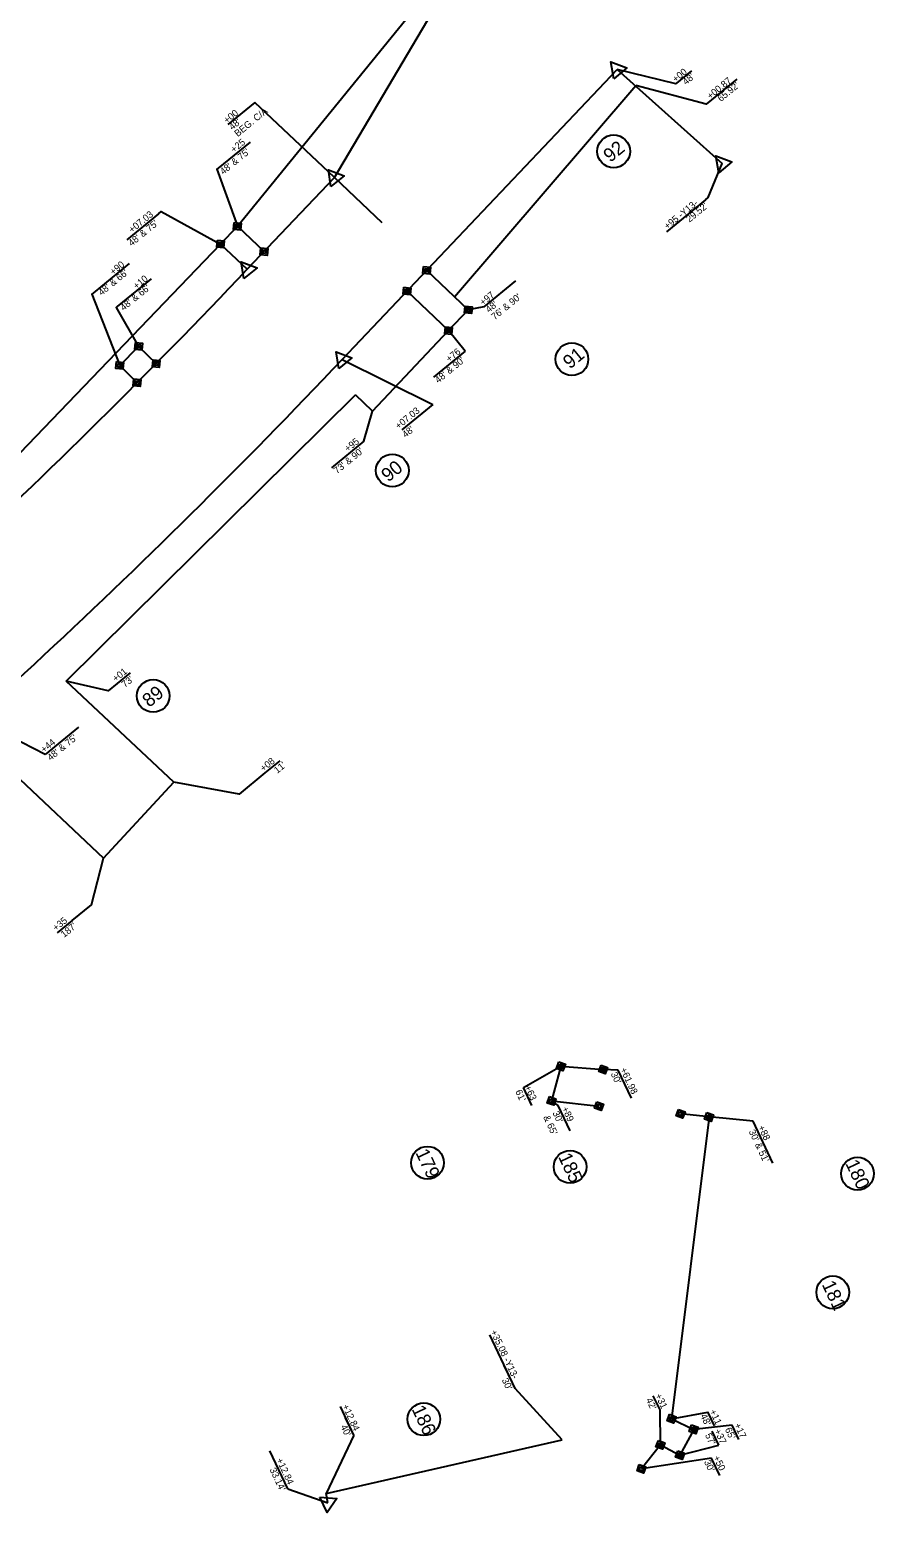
# Model space of a CAD drawing. Extents: x 2320946 to 2332748, y 597838 to 612698.
# Drawn here: x 2327112 to 2327731, y 601762 to 602867 of the extents above; entities that cross this region are included whole.
import ezdxf

# ---------------------------------------------------------------- set-up
doc = ezdxf.new("R2010")
doc.units = 0
for name, color, linetype in [('Prop Easement Construction', 7, 'Continuous'), ('Prop Easement Construction Station Offsets', 7, 'Continuous'), ('Prop Easement Permanent Drainage', 7, 'Continuous'), ('Prop Easement Permanent Drainage Station Offsets', 7, 'Continuous'), ('Prop Easement Permanent Utility', 7, 'Continuous'), ('Prop Easement Permanent Utility Station Offsets', 7, 'Continuous'), ('Prop Parcel Number CELL', 7, 'Continuous'), ('Prop ROW CA Lines', 7, 'Continuous'), ('Prop ROW Marker CELL', 7, 'Continuous'), ('Prop ROW Permanent Easement CELL', 7, 'Continuous'), ('Prop ROW RW CA Lines', 7, 'Continuous'), ('Prop ROW RW Lines', 7, 'Continuous'), ('Prop ROW Station Offsets', 7, 'Continuous')]:
    doc.layers.add(name, color=color, linetype=linetype)

msp = doc.modelspace()

# ---------------------------------------------------------------- linework, layer by layer
at = {"layer": 'Prop Easement Construction'}
for p, q in [((2327264.3, 602723.6), (2327447.9, 602949.2)), ((2327423.4, 602671.9), (2327556.4, 602826.8)), ((2327076.5, 602527.8), (2327252, 602710.5)), ((2327363.3, 602588.1), (2327419.1, 602647.1)), ((2327138.8, 602390.1), (2327350.9, 602599.9)), ((2327363.3, 602588.1), (2327350.9, 602599.9)), ((2327217.8, 602316), (2327138.8, 602390.1)), ((2327100.4, 602322.2), (2327166.1, 602260.3)), ((2327166.1, 602260.3), (2327217.8, 602316)), ((2327329.4, 601794.3), (2327502.5, 601833.7)), ((2327330.7, 601787.6), (2327329.4, 601794.3))]:
    msp.add_line(p, q, dxfattribs=at)
at = {"layer": 'Prop Easement Construction Station Offsets'}
for p, q in [((2327630.5, 602831.4), (2327611.9, 602816.2)), ((2327357.1, 602565.9), (2327333.4, 602546.4)), ((2327185.6, 602396.1), (2327176.1, 602388.3)), ((2327295.4, 602331.6), (2327284.5, 602322.7)), ((2327143.1, 602214.5), (2327132.3, 602205.6)), ((2327465.9, 601875.6), (2327459.9, 601888.3)), ((2327502.5, 601833.7), (2327467.9, 601871.3)), ((2327349.6, 601837.2), (2327343.7, 601849.9)), ((2327349.6, 601837.2), (2327329.4, 601794.3))]:
    msp.add_line(p, q, dxfattribs=at)
for points in [[(2327611.9, 602816.2), (2327608, 602813), (2327556.4, 602826.8)], [(2327357.1, 602565.9), (2327363.3, 602588.1)], [(2327176.1, 602388.3), (2327169.6, 602383), (2327138.8, 602390.1)], [(2327284.5, 602322.7), (2327265.6, 602307.2), (2327217.8, 602316)], [(2327143.1, 602214.5), (2327157.3, 602226.1), (2327166.1, 602260.3)], [(2327467.9, 601871.3), (2327449.3, 601910.7)], [(2327349.6, 601837.2), (2327339.8, 601858.1)]]:
    msp.add_lwpolyline(points, dxfattribs=at)
at = {"layer": 'Prop Easement Permanent Drainage'}
for p, q in [((2327252, 602710.5), (2327264.3, 602723.6)), ((2327264.3, 602723.6), (2327283.9, 602705)), ((2327252, 602710.5), (2327271.5, 602692)), ((2327178.1, 602621.5), (2327191.9, 602635.5)), ((2327191.9, 602635.5), (2327204.8, 602622.9)), ((2327178.1, 602621.5), (2327190.8, 602608.8))]:
    msp.add_line(p, q, dxfattribs=at)
at = {"layer": 'Prop Easement Permanent Drainage Station Offsets'}
for p, q in [((2327273.7, 602785.2), (2327250.3, 602766.2)), ((2327206.5, 602732.7), (2327183.2, 602713.7)), ((2327184.9, 602696.2), (2327160, 602675.8)), ((2327201, 602685), (2327176.1, 602664.7)), ((2327147.8, 602356.2), (2327123.4, 602336.3)), ((2327123.4, 602336.3), (2327097.7, 602349.4))]:
    msp.add_line(p, q, dxfattribs=at)
for points in [[(2327250.3, 602766.2), (2327249.3, 602765.4), (2327264.3, 602723.6)], [(2327206.5, 602732.7), (2327208.4, 602734.3), (2327252, 602710.5)], [(2327160, 602675.8), (2327157.6, 602673.9), (2327178.1, 602621.5)], [(2327176.1, 602664.7), (2327175.5, 602664.1), (2327191.9, 602635.5)]]:
    msp.add_lwpolyline(points, dxfattribs=at)
at = {"layer": 'Prop Easement Permanent Utility'}
for p, q in [((2327433.6, 602662.3), (2327403.1, 602691.2)), ((2327419.1, 602647.1), (2327388.7, 602676)), ((2327419.1, 602647.1), (2327433.6, 602662.3)), ((2327501.5, 602107.6), (2327494.7, 602082.2)), ((2327501.5, 602107.6), (2327532.4, 602105.2)), ((2327494.7, 602082.2), (2327529.5, 602078.4)), ((2327610.1, 602070.5), (2327582.6, 601849.2)), ((2327610.1, 602070.5), (2327589.2, 602072.8)), ((2327582.6, 601849.2), (2327598.9, 601841.4)), ((2327598.9, 601841.4), (2327588.8, 601822.5)), ((2327574.5, 601830), (2327560.5, 601812.4)), ((2327574.5, 601830), (2327588.8, 601822.5))]:
    msp.add_line(p, q, dxfattribs=at)
at = {"layer": 'Prop Easement Permanent Utility Station Offsets'}
for p, q in [((2327468.3, 602683.5), (2327445, 602664.4)), ((2327431.4, 602632.1), (2327408.1, 602613)), ((2327474, 602092.1), (2327501.5, 602107.6)), ((2327553.3, 602084.2), (2327543.6, 602104.8)), ((2327480.2, 602078.9), (2327474, 602092.1)), ((2327499.4, 602078.9), (2327494.7, 602082.2)), ((2327508.2, 602060.2), (2327499.4, 602078.9)), ((2327642.5, 602067.3), (2327610.1, 602070.5)), ((2327656.9, 602036.7), (2327642.5, 602067.3)), ((2327574.2, 601855.6), (2327569.2, 601866.1)), ((2327574.5, 601830), (2327574.2, 601855.6)), ((2327582.6, 601849.2), (2327609.2, 601854.1)), ((2327614, 601843.9), (2327609.1, 601854.3)), ((2327627.1, 601844.4), (2327598.9, 601841.4)), ((2327617.4, 601829.8), (2327612.5, 601840.2)), ((2327632, 601833.9), (2327627.1, 601844.4)), ((2327588.8, 601822.5), (2327617.4, 601829.8)), ((2327611.9, 601820.2), (2327560.5, 601812.4)), ((2327617.9, 601807.5), (2327611.9, 601820.2))]:
    msp.add_line(p, q, dxfattribs=at)
for points in [[(2327445, 602664.4), (2327433.6, 602662.3)], [(2327431.4, 602632.1), (2327419.1, 602647.1)], [(2327543.6, 602104.8), (2327532.4, 602105.2)]]:
    msp.add_lwpolyline(points, dxfattribs=at)
at = {"layer": 'Prop Parcel Number CELL'}
for p, q in [((2327540.2, 602778.5), (2327540.2, 602778.5)), ((2327509.6, 602626.1), (2327509.6, 602626.1)), ((2327377.9, 602544.5), (2327377.9, 602544.5)), ((2327202.6, 602379.2), (2327202.6, 602379.2)), ((2327403.7, 602036.9), (2327403.7, 602036.9)), ((2327508.2, 602033.9), (2327508.2, 602033.9)), ((2327718.9, 602028.9), (2327718.9, 602028.9)), ((2327700.8, 601941.9), (2327700.8, 601941.9)), ((2327401, 601848.8), (2327401, 601848.8))]:
    msp.add_line(p, q, dxfattribs=at)
for centre in [(2327540.2, 602778.5), (2327509.6, 602626.1), (2327377.9, 602544.5), (2327202.6, 602379.2), (2327403.7, 602036.9), (2327508.2, 602033.9), (2327718.9, 602028.9), (2327700.8, 601941.9), (2327401, 601848.8)]:
    msp.add_circle(centre, 12, dxfattribs=at)
at = {"layer": 'Prop ROW CA Lines'}
msp.add_line((2327335.5, 602759.4), (2327370.3, 602726.4), dxfattribs=at)
at = {"layer": 'Prop ROW Marker CELL'}
for p, q in [((2327542.8, 602838.5), (2327542.8, 602838.5)), ((2327619.8, 602769.5), (2327619.8, 602769.5)), ((2327335.5, 602759.4), (2327335.5, 602759.4)), ((2327264.3, 602723.6), (2327264.3, 602723.6)), ((2327252, 602710.5), (2327252, 602710.5)), ((2327283.9, 602705), (2327283.9, 602705)), ((2327271.5, 602692), (2327271.5, 602692)), ((2327403.1, 602691.2), (2327403.1, 602691.2)), ((2327388.7, 602676), (2327388.7, 602676)), ((2327433.6, 602662.3), (2327433.6, 602662.3)), ((2327419.1, 602647.1), (2327419.1, 602647.1)), ((2327191.9, 602635.5), (2327191.9, 602635.5)), ((2327178.1, 602621.5), (2327178.1, 602621.5)), ((2327204.8, 602622.9), (2327204.8, 602622.9)), ((2327341.2, 602625.9), (2327341.2, 602625.9)), ((2327190.8, 602608.8), (2327190.8, 602608.8)), ((2327501.5, 602107.6), (2327501.5, 602107.6)), ((2327532.4, 602105.2), (2327532.4, 602105.2)), ((2327494.7, 602082.2), (2327494.7, 602082.2)), ((2327529.5, 602078.4), (2327529.5, 602078.4)), ((2327589.2, 602072.8), (2327589.2, 602072.8)), ((2327610.1, 602070.5), (2327610.1, 602070.5)), ((2327582.6, 601849.2), (2327582.6, 601849.2)), ((2327598.9, 601841.4), (2327598.9, 601841.4)), ((2327574.5, 601830), (2327574.5, 601830)), ((2327560.5, 601812.4), (2327560.5, 601812.4)), ((2327588.8, 601822.5), (2327588.8, 601822.5)), ((2327330.7, 601787.6), (2327330.7, 601787.6))]:
    msp.add_line(p, q, dxfattribs=at)
for points in [[(2327540.2, 602831.8), (2327538.2, 602844.1), (2327549.9, 602839.7)], [(2327617.2, 602762.8), (2327615.2, 602775.1), (2327626.9, 602770.7)], [(2327332.9, 602752.7), (2327331, 602765), (2327342.6, 602760.6)], [(2327269, 602685.2), (2327267, 602697.5), (2327278.7, 602693.1)], [(2327338.6, 602619.2), (2327336.7, 602631.5), (2327348.3, 602627.1)], [(2327324.8, 601791.7), (2327337.2, 601790.7), (2327330.1, 601780.4)]]:
    msp.add_lwpolyline(points, close=True, dxfattribs=at)
at = {"layer": 'Prop ROW Permanent Easement CELL'}
for points in [[(2327262, 602726.4), (2327267.1, 602725.9), (2327266.6, 602720.8), (2327261.5, 602721.3)], [(2327263.2, 602725), (2327265.7, 602724.7), (2327265.5, 602722.2), (2327262.9, 602722.4)], [(2327249.7, 602713.3), (2327254.7, 602712.8), (2327254.2, 602707.8), (2327249.2, 602708.3)], [(2327250.8, 602711.9), (2327253.3, 602711.7), (2327253.1, 602709.1), (2327250.6, 602709.4)], [(2327281.6, 602707.8), (2327286.7, 602707.3), (2327286.2, 602702.2), (2327281.1, 602702.7)], [(2327282.8, 602706.4), (2327285.3, 602706.1), (2327285, 602703.6), (2327282.5, 602703.9)], [(2327400.8, 602694), (2327405.9, 602693.5), (2327405.4, 602688.4), (2327400.3, 602688.9)], [(2327402, 602692.6), (2327404.5, 602692.3), (2327404.3, 602689.8), (2327401.7, 602690.1)], [(2327386.4, 602678.8), (2327391.5, 602678.2), (2327390.9, 602673.2), (2327385.9, 602673.7)], [(2327387.5, 602677.4), (2327390.1, 602677.1), (2327389.8, 602674.6), (2327387.3, 602674.8)], [(2327431.3, 602665.1), (2327436.4, 602664.6), (2327435.9, 602659.5), (2327430.8, 602660)], [(2327432.5, 602663.7), (2327435, 602663.5), (2327434.7, 602660.9), (2327432.2, 602661.2)], [(2327416.9, 602649.9), (2327421.9, 602649.3), (2327421.4, 602644.3), (2327416.4, 602644.8)], [(2327418, 602648.5), (2327420.5, 602648.2), (2327420.3, 602645.7), (2327417.8, 602645.9)], [(2327189.7, 602638.3), (2327194.7, 602637.8), (2327194.2, 602632.7), (2327189.2, 602633.3)], [(2327190.8, 602636.9), (2327193.3, 602636.7), (2327193.1, 602634.1), (2327190.5, 602634.4)], [(2327175.8, 602624.3), (2327180.8, 602623.8), (2327180.3, 602618.7), (2327175.3, 602619.2)], [(2327176.9, 602622.9), (2327179.5, 602622.6), (2327179.2, 602620.1), (2327176.7, 602620.4)], [(2327202.5, 602625.7), (2327207.5, 602625.2), (2327207, 602620.1), (2327202, 602620.6)], [(2327203.6, 602624.3), (2327206.2, 602624), (2327205.9, 602621.5), (2327203.4, 602621.8)], [(2327188.5, 602611.6), (2327193.6, 602611.1), (2327193.1, 602606), (2327188, 602606.5)], [(2327189.7, 602610.2), (2327192.2, 602610), (2327192, 602607.4), (2327189.4, 602607.7)], [(2327500, 602110.9), (2327504.8, 602109.2), (2327503, 602104.4), (2327498.3, 602106.1)], [(2327500.7, 602109.2), (2327503.1, 602108.4), (2327502.3, 602106), (2327499.9, 602106.9)], [(2327530.9, 602108.5), (2327535.7, 602106.8), (2327534, 602102), (2327529.2, 602103.7)], [(2327531.7, 602106.9), (2327534.1, 602106), (2327533.2, 602103.6), (2327530.8, 602104.5)], [(2327493.1, 602085.5), (2327497.9, 602083.8), (2327496.2, 602079), (2327491.4, 602080.7)], [(2327493.9, 602083.8), (2327496.3, 602083), (2327495.4, 602080.6), (2327493, 602081.5)], [(2327527.9, 602081.6), (2327532.7, 602079.9), (2327531, 602075.1), (2327526.2, 602076.8)], [(2327528.7, 602080), (2327531.1, 602079.1), (2327530.2, 602076.7), (2327527.8, 602077.6)], [(2327587.7, 602076), (2327592.5, 602074.3), (2327590.7, 602069.5), (2327586, 602071.2)], [(2327588.4, 602074.4), (2327590.8, 602073.5), (2327590, 602071.1), (2327587.6, 602072)], [(2327608.6, 602073.7), (2327613.3, 602072), (2327611.6, 602067.2), (2327606.8, 602068.9)], [(2327609.3, 602072.1), (2327611.7, 602071.2), (2327610.9, 602068.8), (2327608.5, 602069.7)], [(2327581.1, 601852.5), (2327585.9, 601850.7), (2327584.1, 601846), (2327579.4, 601847.7)], [(2327581.8, 601850.8), (2327584.2, 601850), (2327583.4, 601847.6), (2327581, 601848.4)], [(2327597.3, 601844.7), (2327602.1, 601843), (2327600.4, 601838.2), (2327595.6, 601839.9)], [(2327598.1, 601843), (2327600.5, 601842.2), (2327599.6, 601839.8), (2327597.2, 601840.7)], [(2327573, 601833.3), (2327577.8, 601831.6), (2327576, 601826.8), (2327571.2, 601828.5)], [(2327573.7, 601831.6), (2327576.1, 601830.8), (2327575.3, 601828.4), (2327572.9, 601829.3)], [(2327587.2, 601825.7), (2327592, 601824), (2327590.3, 601819.2), (2327585.5, 601820.9)], [(2327588, 601824.1), (2327590.4, 601823.2), (2327589.5, 601820.8), (2327587.1, 601821.7)], [(2327559, 601815.7), (2327563.8, 601814), (2327562.1, 601809.2), (2327557.3, 601810.9)], [(2327559.8, 601814.1), (2327562.2, 601813.2), (2327561.3, 601810.8), (2327558.9, 601811.7)]]:
    msp.add_lwpolyline(points, close=True, dxfattribs=at)
at = {"layer": 'Prop ROW RW CA Lines'}
msp.add_line((2327335.5, 602759.4), (2327447.9, 602949.2), dxfattribs=at)
at = {"layer": 'Prop ROW RW Lines'}
for p, q in [((2327341.2, 602625.9), (2327542.8, 602838.5)), ((2327542.8, 602838.5), (2327619.8, 602769.5)), ((2327271.5, 602692), (2327335.5, 602759.4))]:
    msp.add_line(p, q, dxfattribs=at)
for centre, radius, start, end in [((2323721.5, 606057.8), 4892, 309.228, 316.5265), ((2323721.5, 606057.8), 4988, 309.228, 316.5265), ((2326112, 600651.8), 1310, 22.4692, 66.2198)]:
    msp.add_arc(centre, radius, start, end, dxfattribs=at)
at = {"layer": 'Prop ROW Station Offsets'}
for p, q in [((2327597.3, 602837.5), (2327586.3, 602828.5)), ((2327277, 602814.3), (2327257.4, 602798.2)), ((2327335.5, 602759.4), (2327277, 602814.3)), ((2327607.5, 602743), (2327578.8, 602719.6)), ((2327341.2, 602625.9), (2327407.7, 602593)), ((2327407.7, 602593), (2327384.8, 602574.4)), ((2327301.3, 601797.8), (2327288.2, 601825.7)), ((2327301.3, 601797.8), (2327330.7, 601787.6))]:
    msp.add_line(p, q, dxfattribs=at)
for points in [[(2327586.3, 602828.5), (2327585.8, 602828.1), (2327542.8, 602838.5)], [(2327607.5, 602743), (2327609.5, 602744.7), (2327619.8, 602769.5)]]:
    msp.add_lwpolyline(points, dxfattribs=at)

# ---------------------------------------------------------------- texts
at = {"layer": 'Prop Easement Construction Station Offsets'}
for s, rotation, p in [('+00.87', 39.228, (2327611.1, 602816.4)), ("65.92' ", 39.228, (2327618.8, 602814.6)), ('+95', 39.228, (2327345.3, 602557.8)), ("73' & 90'", 39.228, (2327337.4, 602541.7)), ('+01', 39.228, (2327175.2, 602389.2)), ("73'", 39.228, (2327181.9, 602385)), ('+08', 39.228, (2327283.5, 602323.4)), ("11'", 39.228, (2327293.6, 602322)), ('+35', 39.228, (2327131.3, 602206.5)), ("187'", 39.228, (2327137.3, 602201.7)), ('+35.08 -Y13-', 295.2142, (2327449.7, 601913)), ("30'", 295.2142, (2327458, 601877.6)), ('+12.84', 295.2142, (2327341, 601858.4)), ("40'", 295.2142, (2327339.8, 601843.5))]:
    msp.add_text(s, height=5, rotation=rotation, dxfattribs=at).set_placement(p)
at = {"layer": 'Prop Easement Permanent Drainage Station Offsets'}
for s, p in [('+25', (2327261.8, 602777.2)), ("48' & 75'", (2327254, 602761.1)), ('+07.03', (2327187.1, 602718.4)), ("48' & 75'", (2327186.8, 602708.6)), ('+90', (2327173.3, 602687.5)), ("48' & 66' ", (2327164.8, 602672.5)), ('+10', (2327190.4, 602677.1)), ("48' & 66' ", (2327180.9, 602661.3)), ('+44', (2327122.6, 602337.2)), ("48' & 75'", (2327127.4, 602331.4))]:
    msp.add_text(s, height=5, rotation=39.228, dxfattribs=at).set_placement(p)
at = {"layer": 'Prop Easement Permanent Utility Station Offsets'}
for s, rotation, p in [('+97', 39.4097, (2327444.5, 602665.1)), ("76' & 90'", 39.4097, (2327453, 602654.6)), ("48' ", 39.4097, (2327448.8, 602659.9)), ('+76', 39.4097, (2327419.7, 602623.6)), ("48' & 90'", 39.4097, (2327411.6, 602608.2)), ("30'", 295.2158, (2327537.9, 602102.1)), ('+61.98', 295.2158, (2327544.8, 602105.3)), ("61'", 295.2158, (2327467.9, 602089.1)), ('+63', 295.2158, (2327474.7, 602092.3)), ('+89', 295.2158, (2327502, 602076.7)), ("& 65'", 295.2158, (2327488.4, 602070.3)), ("30'", 295.2158, (2327495.2, 602073.5)), ("30' & 51'", 295.2158, (2327639.1, 602059.8)), ('+88', 295.2158, (2327645.9, 602063)), ('+31', 295.2158, (2327570.5, 601866.3)), ("42'", 295.2158, (2327563.7, 601863.1)), ("48'", 295.2158, (2327603.6, 601851.4)), ('+11', 295.2158, (2327610.4, 601854.6)), ('+17', 295.2158, (2327628.4, 601844.6)), ("57'", 295.2158, (2327607, 601837.2)), ('+37', 295.2158, (2327613.8, 601840.4)), ("65'", 295.2158, (2327621.6, 601841.4)), ("30'", 295.2158, (2327606.3, 601817.6)), ('+50', 295.2158, (2327613.1, 601820.8))]:
    msp.add_text(s, height=5, rotation=rotation, dxfattribs=at).set_placement(p)
at = {"layer": 'Prop Parcel Number CELL'}
for s, rotation, p in [('92', 39.228, (2327537.7, 602770)), ('91', 39.228, (2327508.1, 602618.5)), ('90', 39.228, (2327374.9, 602535.6)), ('89', 39.228, (2327199.7, 602370.4)), ('179', 295.2142, (2327394.7, 602044.3)), ('185', 295.2142, (2327499.3, 602041.3)), ('180', 295.2142, (2327709.9, 602036.4)), ('181', 295.2142, (2327692.6, 601947.7)), ('186', 295.2142, (2327391.9, 601856.3))]:
    msp.add_text(s, height=10, rotation=rotation, dxfattribs=at).set_placement(p)
at = {"layer": 'Prop ROW Station Offsets'}
for s, rotation, p in [('+00', 39.228, (2327585.7, 602828.8)), ("48' ", 39.228, (2327593.2, 602826.9)), ('+00', 39.228, (2327256.7, 602798.6)), ('BEG. C/A', 39.228, (2327264.6, 602788.9)), ("48'", 39.228, (2327260.6, 602793.8)), ('+95 -Y13-', 39.228, (2327579.6, 602721)), ("29.52' ", 39.228, (2327595.8, 602726.2)), ('+07.03', 39.228, (2327382.5, 602574.5)), ("48'", 39.228, (2327387.6, 602568.2)), ("33.14'", 295.2142, (2327287.8, 601811.9)), ('+12.84', 295.2142, (2327292.7, 601819))]:
    msp.add_text(s, height=5, rotation=rotation, dxfattribs=at).set_placement(p)

doc.saveas('drawing.dxf')
